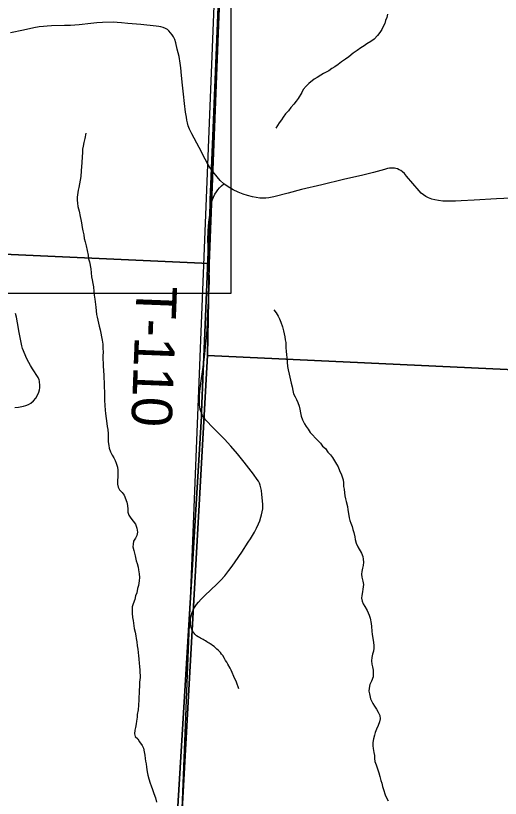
# Model space of a CAD drawing. Extents: x -3.3 to 34, y 0 to 56.8.
# Drawn here: x 1.485 to 2.166, y 31.825 to 32.927 of the extents above; entities that cross this region are included whole.
import ezdxf

# ---------------------------------------------------------------- set-up
doc = ezdxf.new("R2010")
doc.units = 0
for name, color, linetype in [('GM_X_Corporation', 7, 'Continuous'), ('GM_X_County_Road', 7, 'Continuous'), ('GM_X_Township_Road', 7, 'Continuous'), ('GM_X_Township_Road_Text', 7, 'Continuous'), ('GT_Project_Soil_Layers', 7, 'Continuous'), ('SH_Major_Grid_Line', 7, 'Continuous')]:
    doc.layers.add(name, color=color, linetype=linetype)

msp = doc.modelspace()

# ---------------------------------------------------------------- linework, layer by layer
at = {"layer": 'GM_X_Corporation'}
msp.add_line((1.8402, 34.8771), (1.5699, 28.0771), dxfattribs=at)
for points in [[(1.698, 31.5661), (1.7459, 32.363), (1.7461, 32.3685), (1.7485, 32.4264), (1.7493, 32.4459), (1.7554, 32.5941), (1.7581, 32.6599), (1.7584, 32.6672), (1.7602, 32.7115), (1.7831, 33.2694), (1.7901, 33.4394), (1.798, 33.5922), (1.5452, 33.6012), (1.5156, 33.6018), (1.4033, 33.604), (1.3939, 33.6042), (1.3813, 33.6045), (1.268, 33.607), (1.1691, 33.6097), (0.5386, 33.6297), (0.0711, 33.6404), (-0.684, 33.6635)], [(3.4269, 33.3772), (2.8087, 33.3951), (2.6471, 33.398), (2.4136, 33.4064), (2.0441, 33.4254), (1.7901, 33.4394), (1.7831, 33.2694), (1.7602, 32.7115), (1.7584, 32.6672), (1.7581, 32.6599), (1.7554, 32.5941), (1.7493, 32.4459), (1.7485, 32.4264), (1.7461, 32.3685), (1.7459, 32.363), (1.698, 31.5661)]]:
    msp.add_lwpolyline(points, dxfattribs=at)
for points in [[(1.797, 33.5931), (1.7907, 33.4418), (1.757, 32.5776), (0.7357, 32.6242), (0.7743, 33.6261)], [(1.7907, 33.4418), (2.368, 33.4074), (2.7828, 33.3964), (2.7678, 32.4009), (1.7546, 32.4483), (1.757, 32.5776)], [(0.7357, 32.6242), (1.757, 32.5776), (1.7546, 32.4483), (1.7056, 31.5732), (0.6926, 31.6401)], [(1.7546, 32.4483), (2.7678, 32.4009), (2.7235, 31.4121), (1.7022, 31.4496), (1.7056, 31.5732)]]:
    msp.add_lwpolyline(points, close=True, dxfattribs=at)
at = {"layer": 'GM_X_County_Road'}
for points in [[(1.7579, 32.7128), (1.7548, 32.7177), (1.7512, 32.7246), (1.7427, 32.7409), (1.7326, 32.7601), (1.7292, 32.7667), (1.7273, 32.7717), (1.7263, 32.7756), (1.7255, 32.7794), (1.7248, 32.7839), (1.7238, 32.7907), (1.7224, 32.8029), (1.7208, 32.816), (1.7193, 32.8289), (1.718, 32.8425), (1.7169, 32.8531), (1.7161, 32.86), (1.7146, 32.8694), (1.7121, 32.8797), (1.7099, 32.8882), (1.7084, 32.8931), (1.7068, 32.8968), (1.7049, 32.8999), (1.7027, 32.9027), (1.7002, 32.9053), (1.6981, 32.9071), (1.6954, 32.9087), (1.6921, 32.9101), (1.689, 32.911), (1.6862, 32.9116), (1.6824, 32.9121), (1.6608, 32.9141), (1.6425, 32.9158), (1.6336, 32.9166), (1.6277, 32.917), (1.6224, 32.9173), (1.6071, 32.9171), (1.599, 32.9165), (1.5904, 32.9158), (1.5742, 32.914), (1.562, 32.913), (1.5536, 32.9128), (1.5351, 32.9126), (1.5292, 32.9121), (1.5238, 32.9115), (1.518, 32.9108), (1.5102, 32.9094), (1.4959, 32.9063), (1.4777, 32.9023)], [(2.1912, 32.6702), (2.1609, 32.6686), (2.1297, 32.6669), (2.1112, 32.6659), (2.1033, 32.6656), (2.097, 32.6654), (2.0919, 32.6653), (2.0857, 32.6655), (2.0793, 32.6663), (2.0741, 32.6672), (2.0699, 32.6684), (2.0654, 32.6702), (2.0615, 32.6722), (2.0583, 32.6743), (2.0551, 32.6769), (2.0521, 32.6801), (2.0346, 32.7009), (2.0314, 32.7046), (2.0288, 32.707), (2.0264, 32.7087), (2.024, 32.7098), (2.0215, 32.7108), (2.0192, 32.7116), (2.0173, 32.712), (2.0151, 32.7122), (2.0106, 32.712), (2.0078, 32.7114), (2.0034, 32.7102), (1.9882, 32.706), (1.973, 32.7023), (1.9459, 32.6958), (1.9155, 32.6886), (1.8868, 32.6819), (1.868, 32.677), (1.8477, 32.6717), (1.841, 32.6703), (1.8364, 32.6697), (1.8325, 32.6695), (1.8281, 32.6698), (1.823, 32.6705), (1.8176, 32.6715), (1.8106, 32.6734), (1.8045, 32.6754), (1.7975, 32.6783), (1.7907, 32.6816), (1.7838, 32.6856), (1.7773, 32.6901), (1.7725, 32.6947), (1.768, 32.6998), (1.762, 32.7073), (1.7579, 32.7128)]]:
    msp.add_lwpolyline(points, dxfattribs=at)
at = {"layer": 'GM_X_Township_Road'}
for points in [[(1.7522, 32.4644), (1.7536, 32.4772), (1.7544, 32.4949), (1.7551, 32.5094), (1.7558, 32.5246), (1.7569, 32.5426), (1.7574, 32.5527), (1.7571, 32.5707), (1.7564, 32.5831), (1.7557, 32.5951), (1.7553, 32.6035), (1.7552, 32.6105), (1.7555, 32.6239), (1.7565, 32.636), (1.7576, 32.6456), (1.7589, 32.6547), (1.7595, 32.6597), (1.7603, 32.6637), (1.7618, 32.6677), (1.7631, 32.6712), (1.765, 32.6753), (1.767, 32.6785), (1.7689, 32.6815), (1.7712, 32.6844), (1.774, 32.6871), (1.7773, 32.6901)], [(1.4837, 32.375), (1.4889, 32.3756), (1.4935, 32.3763), (1.4959, 32.3768), (1.499, 32.3777), (1.503, 32.3794), (1.506, 32.3812), (1.5097, 32.3842), (1.513, 32.3882), (1.5149, 32.3913), (1.5172, 32.3968), (1.5181, 32.3999), (1.5187, 32.4029), (1.519, 32.4057), (1.5185, 32.4119), (1.5177, 32.4141), (1.5163, 32.417), (1.5083, 32.4296), (1.5057, 32.4339), (1.5031, 32.4384), (1.5006, 32.4433), (1.499, 32.4468), (1.4957, 32.4547), (1.4945, 32.4582), (1.4935, 32.4617), (1.4919, 32.4688), (1.4898, 32.4804), (1.4874, 32.494), (1.4859, 32.502), (1.4847, 32.5073)], [(1.7478, 32.3631), (1.7464, 32.366), (1.7451, 32.3697), (1.7444, 32.3724), (1.7435, 32.3789), (1.7432, 32.3859), (1.7434, 32.3919), (1.7439, 32.3981), (1.7458, 32.4125), (1.7482, 32.4286), (1.7501, 32.4458), (1.7522, 32.4644)], [(1.7363, 32.0936), (1.7392, 32.0978), (1.7418, 32.1008), (1.7457, 32.1051), (1.7503, 32.1099), (1.7596, 32.1187), (1.7674, 32.126), (1.7735, 32.1321), (1.7787, 32.1378), (1.7847, 32.1455), (1.7891, 32.1516), (1.7935, 32.1579), (1.8026, 32.1715), (1.8118, 32.1853), (1.8149, 32.1903), (1.8177, 32.1949), (1.8205, 32.1995), (1.8235, 32.2051), (1.8261, 32.211), (1.828, 32.2156), (1.8297, 32.2206), (1.8307, 32.2241), (1.8316, 32.2283), (1.8322, 32.2321), (1.8324, 32.2356), (1.8323, 32.2391), (1.831, 32.2526), (1.8304, 32.258), (1.8294, 32.2621), (1.8285, 32.2655), (1.8275, 32.2684), (1.8261, 32.2712), (1.8246, 32.2737), (1.819, 32.2812), (1.8061, 32.2982), (1.7968, 32.3099), (1.7874, 32.3206), (1.7783, 32.3304), (1.7625, 32.3462), (1.7523, 32.357), (1.7501, 32.3596), (1.7478, 32.3631)], [(1.7315, 32.0654), (1.7307, 32.0699), (1.7308, 32.0766), (1.7312, 32.0799), (1.732, 32.0832), (1.733, 32.0864), (1.7342, 32.0895), (1.7363, 32.0936)], [(1.7349, 32.0582), (1.7334, 32.0607), (1.7323, 32.063), (1.7315, 32.0654)], [(1.7984, 31.9787), (1.7951, 31.9883), (1.7918, 31.9961), (1.7892, 32.0021), (1.7877, 32.005), (1.7862, 32.0078), (1.7831, 32.0134), (1.7816, 32.0162), (1.78, 32.019), (1.7784, 32.0217), (1.7759, 32.0256), (1.7743, 32.0278), (1.7726, 32.0299), (1.7717, 32.0309), (1.7698, 32.0329), (1.7679, 32.0348), (1.7659, 32.0366), (1.7638, 32.0383), (1.7617, 32.0399), (1.7606, 32.0407), (1.7585, 32.0421), (1.7568, 32.0432), (1.7551, 32.0442), (1.7535, 32.0452), (1.7517, 32.0463), (1.75, 32.0472), (1.7483, 32.0482), (1.7466, 32.0492), (1.7448, 32.0501), (1.7431, 32.051), (1.7413, 32.0519), (1.7392, 32.0535), (1.738, 32.0546), (1.7368, 32.0558), (1.7357, 32.0571), (1.7349, 32.0582)]]:
    msp.add_lwpolyline(points, dxfattribs=at)
at = {"layer": 'GT_Project_Soil_Layers'}
for points in [[(2.0077, 32.9286), (2.0066, 32.924), (2.0048, 32.9198), (2.0037, 32.9156), (2.0015, 32.9114), (1.9996, 32.9072), (1.9971, 32.903), (1.9937, 32.8987), (1.9888, 32.8934), (1.984, 32.8903), (1.9787, 32.8868), (1.9749, 32.884), (1.9704, 32.8813), (1.9652, 32.8778), (1.9592, 32.874), (1.9532, 32.8689), (1.9487, 32.8654), (1.943, 32.8619), (1.9385, 32.8581), (1.9336, 32.8546), (1.9295, 32.8523), (1.925, 32.8492), (1.9175, 32.8453), (1.9137, 32.8429), (1.9088, 32.8398), (1.9047, 32.8375), (1.8972, 32.8313), (1.8935, 32.8274), (1.8893, 32.8228), (1.8871, 32.8186), (1.8819, 32.8102), (1.8793, 32.8063), (1.876, 32.8021), (1.8719, 32.7975), (1.8685, 32.7929), (1.8644, 32.7883), (1.8611, 32.7837), (1.8585, 32.7798), (1.8551, 32.776), (1.8507, 32.7683)], [(1.5834, 32.7613), (1.582, 32.7536), (1.5806, 32.7483), (1.5795, 32.743), (1.5788, 32.7388), (1.5789, 32.7342), (1.5782, 32.7277), (1.5776, 32.7198), (1.577, 32.708), (1.5763, 32.7), (1.5756, 32.695), (1.5746, 32.6897), (1.5735, 32.6847), (1.5728, 32.6809), (1.5714, 32.671), (1.5711, 32.6668), (1.5716, 32.6627), (1.5724, 32.6581), (1.574, 32.6513), (1.5756, 32.6437), (1.5764, 32.6396), (1.5772, 32.635), (1.5785, 32.6286), (1.5793, 32.6236), (1.5805, 32.6183), (1.5813, 32.613), (1.5826, 32.6081), (1.5838, 32.6028), (1.5866, 32.5895), (1.5874, 32.5842), (1.5886, 32.5801), (1.5903, 32.5702), (1.5916, 32.5588), (1.5924, 32.5547), (1.5932, 32.5494), (1.5941, 32.5448), (1.5945, 32.5384), (1.5954, 32.533), (1.5962, 32.5274), (1.5975, 32.5164), (1.5984, 32.5061), (1.5996, 32.502), (1.6024, 32.4895), (1.6036, 32.4845), (1.6065, 32.4698), (1.6073, 32.4641), (1.6074, 32.4576), (1.6078, 32.4538), (1.6075, 32.447), (1.6077, 32.4337), (1.6087, 32.42), (1.6087, 32.4158), (1.6092, 32.4113), (1.6095, 32.3896), (1.6099, 32.3847), (1.61, 32.3783), (1.6105, 32.3707), (1.6109, 32.3669), (1.6117, 32.3627), (1.6126, 32.3563), (1.6135, 32.3483), (1.6143, 32.3441), (1.6147, 32.3377), (1.6149, 32.3267), (1.6157, 32.3214), (1.6162, 32.3176), (1.6181, 32.3126), (1.6205, 32.3077), (1.6228, 32.304), (1.6247, 32.3002), (1.6263, 32.2964), (1.6279, 32.2911), (1.6284, 32.2866), (1.6285, 32.2767), (1.6282, 32.2725), (1.6279, 32.2672), (1.6287, 32.263), (1.6306, 32.2589), (1.6345, 32.2555), (1.6372, 32.2514), (1.6411, 32.2416), (1.6419, 32.237), (1.6424, 32.2317), (1.6424, 32.2275), (1.644, 32.2234), (1.6467, 32.2192), (1.6502, 32.2151), (1.6533, 32.2106), (1.6553, 32.2049), (1.6561, 32.1996), (1.6554, 32.195), (1.6532, 32.1912), (1.6506, 32.187), (1.6499, 32.1824), (1.6496, 32.1786), (1.6508, 32.1737), (1.652, 32.1699), (1.6528, 32.1661), (1.6544, 32.1593), (1.6556, 32.1555), (1.6572, 32.1502)], [(1.8478, 32.5126), (1.8509, 32.5084), (1.854, 32.5035), (1.8556, 32.4997), (1.8575, 32.4952), (1.8599, 32.4888), (1.8615, 32.4827), (1.8631, 32.4744), (1.8636, 32.4702), (1.8647, 32.4664), (1.8649, 32.4588), (1.8653, 32.4543), (1.8657, 32.449), (1.8662, 32.4452), (1.8671, 32.4327), (1.8679, 32.4281), (1.8692, 32.4217), (1.8712, 32.4137), (1.872, 32.4092), (1.8736, 32.4043), (1.8744, 32.3989), (1.8756, 32.3944), (1.8776, 32.3899), (1.8799, 32.3861), (1.8815, 32.382), (1.8834, 32.377), (1.8843, 32.3725), (1.8851, 32.3676), (1.8863, 32.363), (1.8882, 32.3577), (1.891, 32.3521), (1.8933, 32.3483), (1.896, 32.3445), (1.8991, 32.34), (1.9095, 32.3284), (1.9134, 32.3246), (1.9161, 32.3205), (1.9203, 32.3171), (1.9238, 32.3123), (1.9276, 32.3085), (1.9303, 32.3044), (1.933, 32.2998), (1.9361, 32.2953), (1.9381, 32.2916), (1.9404, 32.2863), (1.9428, 32.2802), (1.9452, 32.273), (1.9456, 32.2689), (1.946, 32.2639), (1.9469, 32.2598), (1.9473, 32.2548), (1.9477, 32.2507), (1.9486, 32.2465), (1.9494, 32.2427), (1.9514, 32.2355), (1.9518, 32.231), (1.953, 32.2257), (1.9539, 32.2196), (1.9547, 32.2158), (1.9559, 32.212), (1.9578, 32.2075), (1.959, 32.2034), (1.9602, 32.1988), (1.9618, 32.1931), (1.9622, 32.1893), (1.9635, 32.184), (1.9658, 32.1788), (1.9709, 32.1697), (1.9728, 32.1652), (1.9736, 32.1614), (1.9741, 32.1572), (1.9734, 32.1527), (1.9727, 32.1489), (1.9716, 32.1439), (1.9713, 32.1401), (1.9717, 32.1359), (1.9729, 32.1306), (1.9737, 32.1257), (1.9731, 32.1192), (1.9724, 32.1154), (1.9717, 32.1105), (1.9713, 32.1067), (1.9722, 32.1021), (1.9734, 32.0984), (1.9757, 32.0946), (1.9792, 32.0893), (1.9819, 32.0825), (1.9831, 32.0784), (1.9847, 32.0708), (1.9852, 32.0666), (1.9856, 32.0602), (1.9861, 32.0556), (1.9877, 32.0473), (1.9886, 32.0405), (1.9886, 32.0363), (1.9879, 32.0317), (1.9868, 32.0275), (1.9854, 32.023), (1.9851, 32.0184), (1.9855, 32.0138), (1.9867, 32.0097)], [(1.6572, 32.1502), (1.6576, 32.1465), (1.6584, 32.1408), (1.6589, 32.1358), (1.6586, 32.1309), (1.6575, 32.1244), (1.6561, 32.1202), (1.6554, 32.1141), (1.6535, 32.1096), (1.6525, 32.1046), (1.6499, 32.0985), (1.6488, 32.0943), (1.6485, 32.0905), (1.6486, 32.0856), (1.649, 32.0791), (1.6498, 32.0753), (1.6507, 32.0712), (1.6515, 32.064), (1.6527, 32.0587), (1.6536, 32.0537), (1.6544, 32.0496), (1.6552, 32.045), (1.6556, 32.0393), (1.6568, 32.0348), (1.6577, 32.0253), (1.6582, 32.0212), (1.6586, 32.0147), (1.6591, 32.0109), (1.6595, 32.0048), (1.6597, 31.9946), (1.659, 31.9881), (1.6591, 31.9824), (1.6584, 31.9767), (1.6578, 31.9634), (1.6575, 31.9558), (1.6569, 31.9494), (1.6558, 31.9429), (1.6555, 31.9391), (1.6548, 31.9334), (1.6541, 31.9296), (1.6534, 31.9243), (1.6523, 31.9205), (1.652, 31.9155), (1.6528, 31.9117), (1.6567, 31.9084), (1.659, 31.9042), (1.6629, 31.8993), (1.6644, 31.8952), (1.6653, 31.8903), (1.6665, 31.8854), (1.6669, 31.8808), (1.6673, 31.877), (1.6682, 31.8732), (1.6686, 31.8687), (1.6695, 31.8619), (1.6706, 31.8573), (1.6719, 31.852), (1.6738, 31.846), (1.6754, 31.8422), (1.677, 31.8373), (1.6793, 31.8316), (1.6813, 31.8256), (1.6829, 31.8195)], [(1.9867, 32.0097), (1.9875, 32.0051), (1.9876, 32.0013), (1.9873, 31.9956), (1.9851, 31.9899), (1.9829, 31.985), (1.9818, 31.98), (1.9815, 31.9758), (1.9823, 31.972), (1.9839, 31.9648), (1.987, 31.9584), (1.9894, 31.9543), (1.9921, 31.9502), (1.9944, 31.946), (1.9967, 31.9411), (1.9972, 31.9366), (1.9965, 31.9324), (1.9947, 31.9274), (1.9921, 31.9221), (1.9902, 31.9175), (1.9892, 31.9137), (1.9881, 31.9087), (1.987, 31.9034), (1.9871, 31.8985), (1.9875, 31.8947), (1.9884, 31.8894), (1.9896, 31.8848), (1.9892, 31.8806), (1.9897, 31.8765), (1.9916, 31.8719), (1.9932, 31.8678), (1.9956, 31.8606), (1.9968, 31.8553), (1.9984, 31.8496), (1.9996, 31.8459), (2.0008, 31.8413), (2.002, 31.8372), (2.0043, 31.8296), (2.0063, 31.8254), (2.0086, 31.8213)]]:
    msp.add_lwpolyline(points, dxfattribs=at)
at = {"layer": 'SH_Major_Grid_Line'}
msp.add_lwpolyline([(0.2521, 33.103), (1.7872, 33.103), (1.7872, 32.5355), (0.2521, 32.5355)], close=True, dxfattribs=at)

# ---------------------------------------------------------------- texts
at = {"layer": 'GM_X_Township_Road_Text'}
msp.add_text('T-110', height=0.05682, rotation=267.7544, dxfattribs=at).set_placement((1.6551, 32.5471))

doc.saveas('drawing.dxf')
